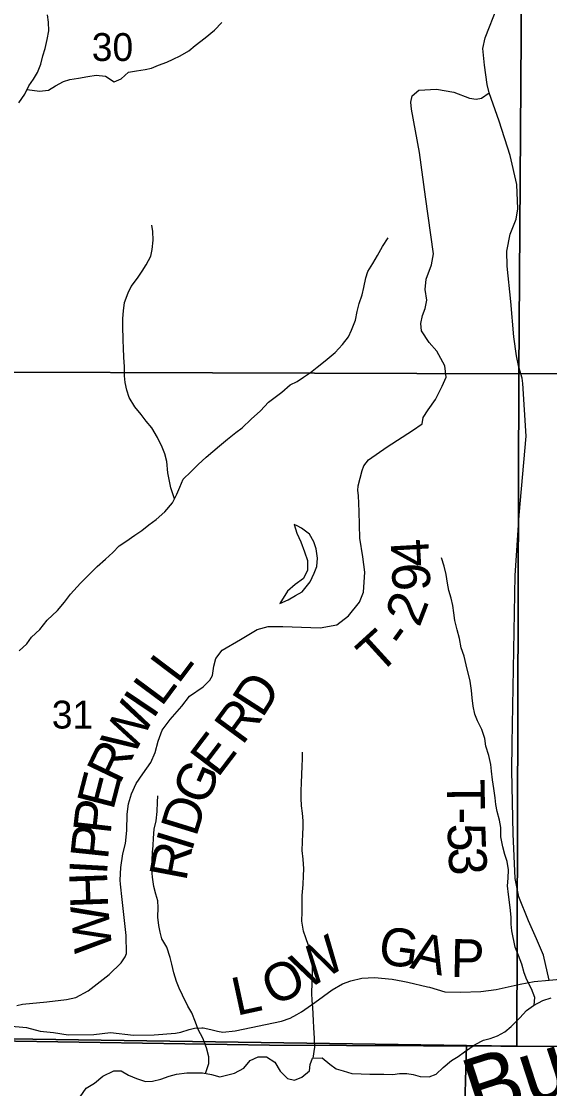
# Model space of a CAD drawing. Extents: x 2043100 to 2470832, y 443715 to 810583.
# Drawn here: x 2260227 to 2264416, y 605936 to 614395 of the extents above; entities that cross this region are included whole.
import ezdxf

# ---------------------------------------------------------------- set-up
doc = ezdxf.new("R2010")
doc.units = 0
for name, color, linetype in [('GM_X_County_Road', 7, 'Continuous'), ('GM_X_County_Road_Text', 7, 'Continuous'), ('GM_X_Minor_Lake', 7, 'Continuous'), ('GM_X_Minor_River', 7, 'Continuous'), ('GM_X_Minor_River_Text', 7, 'Continuous'), ('GM_X_Section', 7, 'Continuous'), ('GM_X_Section_Text', 7, 'Continuous'), ('GM_X_Township', 7, 'Continuous'), ('GM_X_Township_Road', 7, 'Continuous'), ('GM_X_Township_Road_Text', 7, 'Continuous'), ('GM_X_Township_ROW', 7, 'Continuous')]:
    doc.layers.add(name, color=color, linetype=linetype)

msp = doc.modelspace()

# ---------------------------------------------------------------- linework, layer by layer
at = {"layer": 'GM_X_County_Road'}
msp.add_lwpolyline([(2260121.5, 606433.5), (2260267.5, 606419.4), (2260377, 606390.7), (2260483.6, 606380.5), (2260598.3, 606363.1), (2260801, 606366.2), (2260934.2, 606380.5), (2261115.8, 606360.4), (2261279.8, 606363.4), (2261449.6, 606374.6), (2261491.5, 606383.4), (2261557.1, 606404.6), (2261600.9, 606415.4), (2261658.8, 606418.5), (2261669.6, 606416.5), (2261729.1, 606405.8), (2261781.4, 606390.7), (2261825.5, 606383.5), (2261921.3, 606395.2), (2262290, 606470.1), (2262357.6, 606493.4), (2262410.3, 606523.4), (2262448.7, 606545.2), (2262553.4, 606619.3), (2262691.6, 606720), (2262772.8, 606767.6), (2262840.4, 606790.9), (2262926, 606810.5), (2263025.9, 606816.3), (2263166.2, 606802.9), (2263250.5, 606787), (2263292.6, 606779.1), (2263447.3, 606743.9), (2263462.7, 606739.5), (2263586, 606704.3), (2263708.1, 606700.5), (2263870.1, 606705.5), (2263991.8, 606721.8), (2264183.1, 606763.4), (2264292.7, 606785.4), (2264410.7, 606796.8), (2264734.1, 606823.5)], dxfattribs=at)
at = {"layer": 'GM_X_Minor_Lake'}
for points in [[(2262414.6, 610396.4), (2262391.3, 610408.4), (2262411.6, 610338.4), (2262442, 610270.4), (2262472.4, 610190.4), (2262496.8, 610122.4), (2262497.1, 610046.3), (2262465.4, 609980), (2262399.4, 609931.7), (2262337.5, 609879.3), (2262277.8, 609780.9)], [(2262277.8, 609780.9), (2262343.8, 609809.2), (2262401.8, 609843.5), (2262453.8, 609873.8), (2262517.6, 609952.2), (2262549.4, 610022.5), (2262569.2, 610074.7), (2262574.9, 610140.8), (2262564.6, 610214.8), (2262546.3, 610268.9), (2262511.9, 610330.8), (2262449.6, 610378.6), (2262414.6, 610396.4)]]:
    msp.add_lwpolyline(points, dxfattribs=at)
at = {"layer": 'GM_X_Minor_River'}
for points in [[(2260207.7, 613748.9), (2260255.4, 613817.3), (2260287, 613883.6), (2260322.8, 613935.9), (2260354.5, 613990.2), (2260382.1, 614054.5), (2260397.7, 614122.8), (2260415.4, 614179), (2260431, 614251.2), (2260444.5, 614319.4), (2260444.1, 614389.5), (2260433.7, 614445.6)], [(2260273.4, 613855.1), (2260371.5, 613842.1), (2260441.6, 613848.6), (2260499.5, 613885), (2260561.5, 613919.5), (2260611.5, 613933.8), (2260679.6, 613944.3), (2260755.7, 613958.8), (2260819.8, 613967.3), (2260894, 613961.7), (2260964.4, 613916.1), (2261018.4, 613940.5), (2261078.2, 613991), (2261140.3, 614003.4), (2261210.4, 614013.9), (2261260.4, 614024.2), (2261314.4, 614046.6), (2261380.4, 614071.1), (2261432.4, 614095.5), (2261486.3, 614121.9), (2261554.2, 614160.4), (2261606.1, 614202.8), (2261683.9, 614265.4), (2261757.7, 614324), (2261817.4, 614386.5)], [(2261442, 610610.3), (2261412.7, 610697.7), (2261400.2, 610763.8), (2261389.8, 610817.8), (2261381.2, 610905.9), (2261364.8, 610967.8), (2261344.4, 611019.8), (2261305.8, 611097.7), (2261261.2, 611173.5), (2261216.7, 611227.3), (2261178.3, 611279.1), (2261127.8, 611338.9), (2261083.2, 611414.7), (2261062.7, 611470.7), (2261050.3, 611532.7), (2261044, 611584.7), (2261045.5, 611656.8), (2261039, 611732.9), (2261036.5, 611805), (2261034.1, 611869.1), (2261033.3, 611981.3), (2261030.9, 612039.4), (2261036.5, 612101.5), (2261046.1, 612165.7), (2261073.7, 612242), (2261099.4, 612294.2), (2261147.1, 612358.7), (2261184.8, 612415), (2261216.6, 612465.3), (2261254.2, 612533.7), (2261265.9, 612585.8), (2261273.4, 612660), (2261271, 612730.1), (2261262.6, 612780.1)], [(2262941.9, 612284.3), (2262957.4, 612362.6), (2262975.1, 612412.8), (2263014.8, 612475.1), (2263050.5, 612539.5), (2263090.1, 612609.8), (2263135.8, 612678.2)], [(2260210.3, 609405.9), (2260272.1, 609460.4), (2260307.8, 609514.7), (2260373.6, 609575.2), (2260433.2, 609647.7), (2260514.9, 609726.4), (2260568.6, 609790.8), (2260618.3, 609855.2), (2260695.9, 609941.9), (2260765.6, 610010.4), (2260827.4, 610074.9), (2260895.2, 610131.5), (2260952.9, 610183.9), (2261002.7, 610238.3), (2261056.6, 610272.8), (2261128.4, 610323.3), (2261182.3, 610359.7), (2261238.2, 610404.2), (2261296, 610446.6), (2261365.8, 610507.1), (2261425.5, 610577.6), (2261461.1, 610648), (2261482.8, 610702.2), (2261510.4, 610766.5), (2261570.2, 610825), (2261630, 610883.5), (2261693.7, 610942), (2261745.6, 610984.4), (2261799.4, 611030.8), (2261861.2, 611083.3), (2261927, 611135.8), (2261978.9, 611174.2), (2262050.6, 611240.8), (2262124.4, 611307.4), (2262188, 611377.9), (2262239.9, 611416.3), (2262291.8, 611456.7), (2262357.6, 611513.2), (2262413.5, 611541.7), (2262465.4, 611576), (2262519.3, 611612.5), (2262573.2, 611652.9), (2262635, 611705.4), (2262714.7, 611770), (2262774.4, 611834.5), (2262820.1, 611894.9), (2262843.9, 611947.1), (2262875.4, 612027.5), (2262889, 612095.7), (2262906.6, 612157.9), (2262930.2, 612228.2), (2262941.9, 612284.3)], [(2264293.7, 606598.3), (2264298.1, 606658.7), (2264271.6, 606726.6), (2264235, 606798.5), (2264214.6, 606854.4), (2264196.1, 606922.4), (2264167.6, 606990.3), (2264143.1, 607056.3), (2264116.2, 607186.3), (2264111.8, 607238.3), (2264109.5, 607292.4), (2264105.1, 607348.4), (2264096.6, 607412.5), (2264088.2, 607474.5), (2264081.8, 607542.6), (2264087.4, 607604.7), (2264088.9, 607670.8), (2264078.5, 607736.8), (2264060.1, 607790.8), (2264043.6, 607852.8), (2264029.1, 607930.8), (2264028.6, 608004.9), (2264018.2, 608062.9), (2263999.7, 608132.9), (2263989.3, 608188.9), (2263982.9, 608240.9), (2263972.4, 608315), (2263962, 608383), (2263955.5, 608451), (2263949.1, 608505.1), (2263934.6, 608575.1), (2263910.1, 608651), (2263901.7, 608711.1), (2263877.1, 608783), (2263842.6, 608850.9), (2263822.2, 608904.8), (2263809.8, 608966.8), (2263801.3, 609032.9), (2263794.9, 609090.9), (2263784.4, 609165), (2263753.5, 609295), (2263737, 609363), (2263714.5, 609430.9), (2263700, 609502.9), (2263681.5, 609572.9), (2263662.9, 609646.9), (2263656.5, 609706.9), (2263648.1, 609765), (2263635.7, 609823), (2263617.3, 609883), (2263606.9, 609943), (2263594.4, 610011), (2263579.9, 610077), (2263559.4, 610143)], [(2262541.8, 606176.9), (2262554.5, 606264.8), (2262552, 606334.8), (2262545.5, 606418.9), (2262543.1, 606475), (2262538.4, 606579.1), (2262532, 606633.1), (2262531.6, 606693.2), (2262533.1, 606775.3), (2262536.7, 606837.4), (2262536, 606947.6), (2262523.6, 606999.6), (2262503.1, 607069.5), (2262482.6, 607131.5), (2262464.3, 607183.4), (2262451.7, 607263.5), (2262453.2, 607337.6), (2262454.7, 607415.7), (2262454.4, 607465.8), (2262461.8, 607554), (2262465.4, 607622.1), (2262467, 607678.2), (2262460.5, 607754.2), (2262454, 607822.3), (2262455.6, 607892.4), (2262459.2, 607954.5), (2262462.9, 608004.6), (2262462.5, 608058.7), (2262456.1, 608118.7), (2262447.7, 608176.8), (2262445.3, 608238.8), (2262446.9, 608294.9), (2262448.5, 608359), (2262452.1, 608425.2), (2262453.6, 608491.2), (2262457.3, 608549.4), (2262456.9, 608603.4)], [(2261687.1, 606056.8), (2261713.4, 606135.1), (2261715, 606187.1), (2261696.5, 606259.1), (2261665.9, 606335), (2261629.4, 606404.9), (2261609, 606462.8), (2261578.4, 606536.7), (2261548, 606590.6), (2261505.3, 606676.4), (2261478.9, 606732.3), (2261456.5, 606786.3), (2261436, 606854.2), (2261419.5, 606922.2), (2261407.1, 606974.2), (2261380.5, 607056.2), (2261342, 607124), (2261327.6, 607176), (2261317.2, 607228), (2261308.8, 607294), (2261312.3, 607370.2), (2261309.9, 607424.2), (2261293.5, 607476.2), (2261277.1, 607538.2), (2261266.6, 607612.2), (2261262.2, 607676.3), (2261265.7, 607748.4), (2261267.3, 607806.5), (2261273, 607862.6), (2261274.6, 607920.7), (2261280.1, 607992.8), (2261295.7, 608059), (2261303.3, 608131.2), (2261306.8, 608207.3), (2261310.5, 608257.4)], [(2260694.7, 605872), (2260742.3, 605940.4), (2260806.2, 605978.9), (2260874, 606033.4), (2260962, 606076.1), (2261020.1, 606076.4), (2261076.4, 606042.8), (2261140.8, 606015.2), (2261211.1, 605993.6), (2261267.2, 605995.9), (2261333.3, 606010.4), (2261399.3, 606034.9), (2261457.3, 606049.3), (2261539.4, 606059.8), (2261663.7, 606060.6), (2261734, 606049.1), (2261802.3, 606029.5), (2261864.3, 606045.9), (2261916.3, 606058.3), (2261992.3, 606096.8), (2262042, 606159.2), (2262103.9, 606187.7), (2262170.1, 606188.1), (2262236.5, 606146.5), (2262279.1, 606074.7), (2262337.6, 606015), (2262391.8, 606003.3), (2262449.8, 606025.7), (2262511.7, 606076.2), (2262517.3, 606126.3), (2262535, 606176.5), (2262613.2, 606181), (2262673.7, 606129.3), (2262724, 606093.6), (2262778.3, 606075.9), (2262846.6, 606056.4), (2262920.8, 606052.8), (2262989, 606049.3), (2263101.2, 606050), (2263173.4, 606048.5), (2263225.5, 606054.8), (2263283.6, 606055.2), (2263333.8, 606047.5), (2263388, 606031.9), (2263460.2, 606028.3), (2263516.2, 606050.8), (2263572, 606103.2), (2263637.8, 606157.7), (2263689.7, 606190.1), (2263741.6, 606226.5), (2263825.4, 606285.1), (2263891.3, 606319.6), (2263943.4, 606333.9), (2264001.4, 606354.3), (2264059.3, 606386.8), (2264111.2, 606427.2), (2264178.9, 606495.7), (2264232.6, 606554.1), (2264286.5, 606594.5), (2264360.4, 606633.1), (2264428.4, 606655.6)]]:
    msp.add_lwpolyline(points, dxfattribs=at)
at = {"layer": 'GM_X_Section'}
for points in [[(2257753.6, 616880.4), (2264207.2, 616970.4), (2264172.3, 611601.8), (2257691.4, 611621.5), (2257692.8, 611847.6)], [(2269527.4, 616965), (2269496.5, 611606.4), (2264172.3, 611601.8), (2264207.2, 616970.4)], [(2264172.3, 611601.8), (2264155, 606271.4), (2263756.8, 606278.7), (2257601.2, 606366.3), (2257691.4, 611621.5)], [(2264172.3, 611601.8), (2269496.5, 611606.4), (2269441.5, 606251.6), (2269343.4, 606254.4), (2264155, 606271.4)], [(2263756.8, 606278.7), (2263608.5, 601036.8), (2257596.4, 601170.1), (2257566.4, 604734.7), (2257601.2, 606366.3)], [(2264155, 606271.4), (2269343.4, 606254.4), (2269267.4, 600979.4), (2263608.5, 601036.8), (2263756.8, 606278.7)]]:
    msp.add_lwpolyline(points, close=True, dxfattribs=at)
at = {"layer": 'GM_X_Township'}
for points in [[(2272583, 606236.7), (2262194.9, 606279.1), (2259171.6, 606328.3), (2258912.7, 606347.4), (2257596.4, 606358.1), (2257624.6, 606994.4), (2257653.2, 607589.5), (2257760.5, 615186.1), (2257992.6, 628603.2), (2258081.3, 633732.5)], [(2271279.8, 595728.8), (2265161.1, 595808.6), (2263459.7, 595834.9), (2263491.4, 596564.4), (2263552.9, 601003.2), (2261734.4, 601044.3), (2261076.2, 601059.3), (2259770.8, 601088.8), (2258944.2, 601107.5), (2257611.2, 601163.6), (2257603, 601401.2), (2257579.2, 602655.8), (2257574, 602803.7), (2257564.9, 604475.8), (2257568.4, 604957), (2257562.2, 605061.7), (2257563.6, 605306.8), (2257565.4, 605638.9), (2257596.4, 606358.1), (2258912.7, 606347.4), (2259171.6, 606328.3), (2262194.9, 606279.1), (2272583, 606236.7)]]:
    msp.add_lwpolyline(points, dxfattribs=at)
at = {"layer": 'GM_X_Township_Road'}
for points in [[(2260190.5, 606593.9), (2260236.5, 606604.1), (2260428.5, 606624.9), (2260586.6, 606643.5), (2260660.6, 606657.8), (2260758.5, 606710.3), (2260924.1, 606839.3), (2261017.9, 606931.8), (2261051.8, 606980.1), (2261061.7, 607008.2), (2261059.2, 607150.5), (2261026.3, 607435), (2261013.9, 607555.2), (2261011.8, 607589.3), (2261017.4, 607687.5), (2261031.1, 607795.8), (2261052.8, 607878.1), (2261064.5, 607982.4), (2261066.1, 608110.7), (2261077.8, 608192.9), (2261099.6, 608271.2), (2261137.4, 608355.5), (2261191.1, 608431.9), (2261252.9, 608520.3), (2261288.7, 608600.7), (2261312.4, 608688.9), (2261344.1, 608777.3), (2261407.9, 608861.7), (2261499.6, 608968.3), (2261561.4, 609046.7), (2261669.2, 609119.3), (2261721.1, 609173.7), (2261743, 609209.8), (2261754.7, 609284.1), (2261768.5, 609346.2), (2261818.4, 609410.6), (2261964.2, 609495.4), (2262098, 609576.1), (2262184, 609598.5), (2262300, 609598.9), (2262596.3, 609588.1), (2262728.3, 609612.6), (2262820.1, 609683.1), (2262907.8, 609791.7), (2262939.6, 609872.1), (2262951.1, 610028.5), (2262934.7, 610150.7), (2262912.2, 610298.9), (2262905.5, 610511.4), (2262901.1, 610635.7), (2262894.9, 610677.8), (2262896.8, 610713.9), (2262928.4, 610836.3), (2262942.3, 610872.4), (2262980.2, 610918.7), (2263127.9, 611023.5), (2263327.6, 611152.6), (2263405.5, 611205), (2263413.4, 611255.2), (2263453.2, 611315.5), (2263511, 611397.9), (2263564.7, 611504.4), (2263594.4, 611574.7), (2263584.1, 611664.9), (2263521.7, 611780.9), (2263461.5, 611848.8), (2263401.1, 611942.8), (2263394.9, 612000.9), (2263406.7, 612063.1), (2263428.6, 612119.4), (2263442.4, 612185.6), (2263430.1, 612269.7), (2263435.8, 612352), (2263479.5, 612466.4), (2263495.2, 612552.7), (2263431.7, 613003.6), (2263384.5, 613356.3), (2263321.4, 613698.9), (2263315.2, 613755), (2263325, 613805.2), (2263378.9, 613849.5), (2263519, 613858.1), (2263657.1, 613832.5), (2263779.4, 613786.9), (2263833.4, 613779.1), (2263875.4, 613785.3), (2263937.3, 613827.6), (2263921.1, 613895.7), (2263898.6, 614048), (2263886.2, 614180.3), (2263903.9, 614264.6), (2264001.1, 614513.6)], [(2264310.8, 607123.5), (2264248.9, 607265.2), (2264172.2, 607457.3), (2264141.7, 607601.5), (2264126.6, 607954.3), (2264114.9, 608457.4), (2264118.6, 608670.3), (2264118.6, 608671.1)], [(2264410.7, 606796.8), (2264367.8, 606993), (2264311.1, 607122.9), (2264310.8, 607123.5)]]:
    msp.add_lwpolyline(points, dxfattribs=at)
at = {"layer": 'GM_X_Township_ROW'}
msp.add_lwpolyline([(2264118.6, 608671.1), (2264141.9, 610003.1), (2264174.4, 610482.3), (2264230.4, 611108), (2264203, 611524.9), (2264196.9, 611567), (2264172.6, 611653.1), (2264152.3, 611743.3), (2264131.7, 611895.6), (2264106.8, 612174.1), (2264079.9, 612454.7), (2264075.5, 612573), (2264103.1, 612707.4), (2264150.7, 612827.9), (2264164.5, 612910.2), (2264155.8, 613102.6), (2264103, 613333), (2264016.1, 613603.3), (2263937.3, 613827.6)], dxfattribs=at)

# ---------------------------------------------------------------- texts
at = {"layer": 'GM_X_County_Road_Text'}
for s, rotation, p in [('G', 352.04403, (2263047.6, 606928.7)), ('W', 31.36417, (2262491.9, 606715.1)), ('A', 346.33396, (2263301.3, 606893.7)), ('P', 358.98983, (2263629.4, 606822.1)), ('O', 25.69758, (2262225.5, 606585.2)), ('L', 12.20341, (2261933.4, 606512.8))]:
    msp.add_text(s, height=300, rotation=rotation, dxfattribs=at).set_placement(p)
at = {"layer": 'GM_X_Minor_River_Text'}
msp.add_text('Buffalo', height=499.98, rotation=18.00147, dxfattribs=at).set_placement((2263834.2, 605666.1))
at = {"layer": 'GM_X_Section_Text'}
for s, p in [('30', (2260785.8, 614081)), ('31', (2260469, 608790))]:
    msp.add_text(s, height=220.83, rotation=0.00001, dxfattribs=at).set_placement(p)
at = {"layer": 'GM_X_Township_Road_Text'}
for s, rotation, p in [('4', 93.17142, (2263465.6, 610078.2)), ('9', 91.33081, (2263470.3, 609882.9)), ('2', 69.03428, (2263382.6, 609585.7)), ('T', 42.35959, (2263059.8, 609209.8)), ('-', 54.27859, (2263270.8, 609411.8)), ('L', 52.99553, (2261471.8, 609136.1)), ('L', 53.43951, (2261338.5, 608956.3)), ('D', 57.37874, (2262137.7, 608866.4)), ('I', 56.04146, (2261271.7, 608857.1)), ('W', 61.66289, (2261110.8, 608557.8)), ('R', 53.73493, (2261980.1, 608650.5)), ('E', 52.73582, (2261784.8, 608393.8)), ('R', 64.4613, (2261006.3, 608338.9)), ('G', 66.27718, (2261688.1, 608168.2)), ('E', 75.49289, (2260955.3, 608136)), ('T', 270.62141, (2263600.3, 608389)), ('D', 72.86566, (2261613.5, 607924.4)), ('P', 83.51445, (2260934.5, 607945.8)), ('-', 271.00956, (2263602.8, 608162.4)), ('P', 84.0166, (2260913.4, 607745.2)), ('5', 271.8755, (2263605.1, 608034.3)), ('I', 72.91792, (2261577.3, 607806.7)), ('R', 79.28252, (2261533.6, 607573.2)), ('3', 273.18457, (2263611.5, 607842.1)), ('I', 86.86043, (2260907, 607626.1)), ('H', 92.106, (2260916.8, 607369.5)), ('W', 95.41135, (2260949.2, 607028.1))]:
    msp.add_text(s, height=300, rotation=rotation, dxfattribs=at).set_placement(p)

doc.saveas('drawing.dxf')
